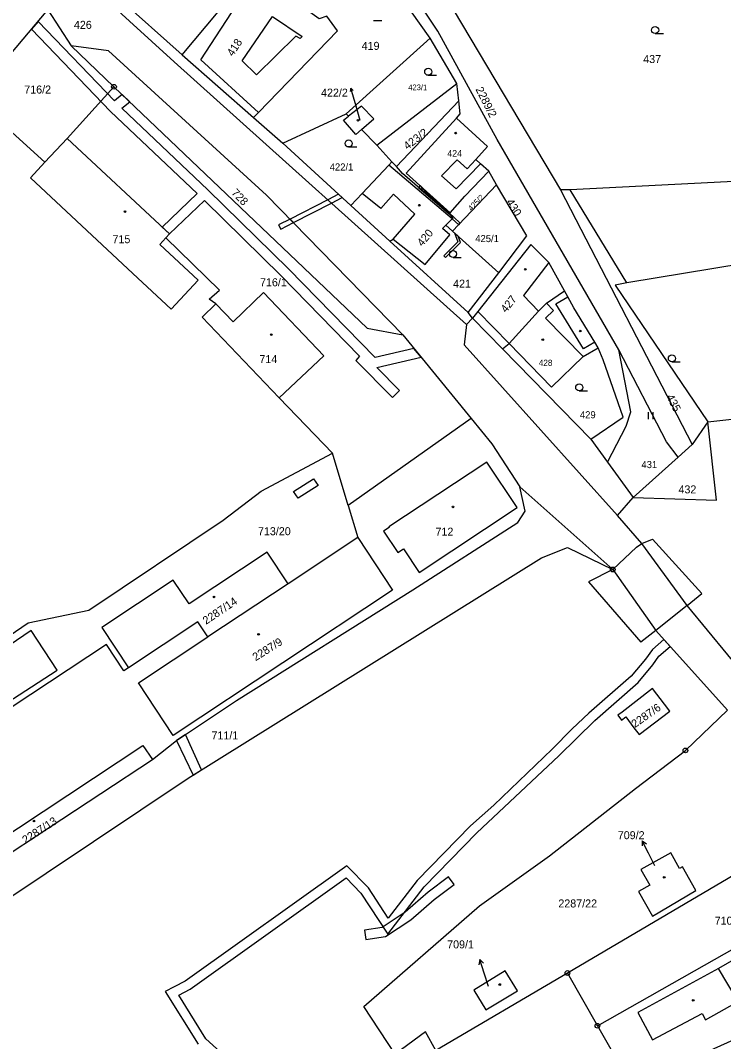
# Model space of a CAD drawing. Extents: x -504988 to -494607, y -1123820 to -1114018.
# Drawn here: x -496997.3 to -496848, y -1120700.3 to -1120483.5 of the extents above; entities that cross this region are included whole.
import ezdxf

# ---------------------------------------------------------------- set-up
doc = ezdxf.new("R2010")
doc.units = 0
for name, color, linetype in [('Hranice parcel', 7, 'Continuous'), ('Parcelní čísla', 7, 'Continuous'), ('Pop  PČ popisy', 7, 'Continuous'), ('Vnitřní kresba', 7, 'Continuous'), ('Věcná břemena k části', 7, 'Continuous'), ('Značky bodu BP', 7, 'Continuous'), ('Značky budov', 7, 'Continuous'), ('Značky kultur', 7, 'Continuous')]:
    doc.layers.add(name, color=color, linetype=linetype)

msp = doc.modelspace()

# ---------------------------------------------------------------- linework, layer by layer
at = {"layer": 'Hranice parcel'}
for p, q in [((-496910.28, -1120487.25), (-496931.3, -1120457.35)), ((-496980.45, -1120475.17), (-496962.91, -1120490.84)), ((-496962.91, -1120490.84), (-496949.37, -1120474.55)), ((-496991.45, -1120481.25), (-496986.51, -1120488.92)), ((-496928.11, -1120503.32), (-496910.28, -1120487.25)), ((-496904.62, -1120496.92), (-496910.28, -1120487.25)), ((-496986.51, -1120488.92), (-496977.41, -1120497.6)), ((-496962.91, -1120490.84), (-496947.76, -1120504.11)), ((-496921.6, -1120510.03), (-496904.62, -1120496.92)), ((-496904.23, -1120500.55), (-496904.62, -1120496.92)), ((-496977.41, -1120497.6), (-496987.36, -1120508.57)), ((-496992.06, -1120513.61), (-497007.31, -1120499.8)), ((-496917.46, -1120514.56), (-496904.23, -1120500.55)), ((-496941.57, -1120509.54), (-496928.11, -1120503.32)), ((-496927.59, -1120503.85), (-496928.11, -1120503.32)), ((-496947.76, -1120504.11), (-496941.57, -1120509.54)), ((-496921.6, -1120510.03), (-496924.83, -1120506.7)), ((-496987.36, -1120508.57), (-496992.06, -1120513.61)), ((-496941.57, -1120509.54), (-496927.11, -1120522.81)), ((-496918.41, -1120513.52), (-496921.6, -1120510.03)), ((-496917.46, -1120514.56), (-496918.41, -1120513.52)), ((-496916.13, -1120516), (-496917.46, -1120514.56)), ((-496906.26, -1120524.61), (-496916.13, -1120516)), ((-496896.17, -1120518.4), (-496897.86, -1120515.55)), ((-496811.5, -1120515.9), (-496880.58, -1120519.51)), ((-496896.17, -1120518.4), (-496905.52, -1120528.27)), ((-496882.64, -1120519.48), (-496854.69, -1120573.54)), ((-496880.58, -1120519.51), (-496882.64, -1120519.48)), ((-496868.53, -1120539.24), (-496880.58, -1120519.51)), ((-496927.11, -1120522.81), (-496918.88, -1120530.35)), ((-496905.45, -1120525.46), (-496906.26, -1120524.61)), ((-496905.52, -1120528.27), (-496906.95, -1120526.98)), ((-496895.69, -1120537.14), (-496905.52, -1120528.27)), ((-496918.88, -1120530.35), (-496902.22, -1120545.55)), ((-496902.22, -1120545.55), (-496895.69, -1120537.14)), ((-496901.27, -1120546.76), (-496902.22, -1120545.55)), ((-496901.27, -1120546.76), (-496894.93, -1120553.22)), ((-496916.08, -1120550.26), (-496901.56, -1120568.05)), ((-496894.93, -1120553.22), (-496893.52, -1120552.12)), ((-496894.93, -1120553.22), (-496876.16, -1120572.45)), ((-496930.99, -1120575.43), (-496942.31, -1120563.63)), ((-496901.56, -1120568.05), (-496927.7, -1120586.53)), ((-496851.36, -1120568.74), (-496854.69, -1120573.54)), ((-496851.36, -1120568.74), (-496840.65, -1120567.59)), ((-496876.16, -1120572.45), (-496872.63, -1120577.3)), ((-496946.16, -1120583.5), (-496930.99, -1120575.43)), ((-496927.7, -1120586.53), (-496930.99, -1120575.43)), ((-496854.69, -1120573.54), (-496857.65, -1120576.22)), ((-496872.63, -1120577.3), (-496867.16, -1120584.83)), ((-496867.16, -1120584.83), (-496857.65, -1120576.22)), ((-496891.25, -1120582.52), (-496871.51, -1120600.1)), ((-496927.7, -1120586.53), (-496925.65, -1120593.33)), ((-496925.65, -1120593.33), (-496940.42, -1120603.11)), ((-496940.42, -1120603.11), (-496957.48, -1120614.37)), ((-497003.77, -1120617.01), (-496995.6, -1120611.41)), ((-496856.1, -1120638.53), (-496847.18, -1120629.97)), ((-496971.29, -1120637.49), (-496969.26, -1120640.45)), ((-497022.21, -1120675.27), (-496969.26, -1120640.45)), ((-496823.76, -1120652.04), (-496881.14, -1120685.78)), ((-496874.78, -1120696.97), (-496812.85, -1120661.83)), ((-496881.14, -1120685.78), (-496874.78, -1120696.97)), ((-496917.69, -1120703), (-496924.38, -1120692.87))]:
    msp.add_line(p, q, dxfattribs=at)
for points in [[(-497083.51, -1120361.17), (-497068.27, -1120386.21), (-497064.86, -1120391.23), (-497055.98, -1120403.1), (-497051.98, -1120408.19), (-497036.29, -1120426.16), (-497025.6, -1120436.78), (-496964.64, -1120492.27), (-496902.58, -1120548.07), (-496901.27, -1120546.76)], [(-496870.25, -1120553.45), (-496896.08, -1120508.78), (-496908.69, -1120485.78), (-496920.45, -1120468), (-496933.79, -1120454.35), (-496940.92, -1120450.89), (-496953.48, -1120444.28)], [(-496912.61, -1120469.68), (-496905.22, -1120481.57), (-496882.64, -1120519.48)], [(-496947.76, -1120504.11), (-496946.75, -1120503.07), (-496929.97, -1120485.74), (-496932.25, -1120482.63), (-496933.87, -1120483.18), (-496936.3, -1120481.41), (-496935.13, -1120479.23), (-496940.4, -1120475.68), (-496942.89, -1120479.14), (-496948.48, -1120475.73), (-496949.37, -1120474.55)], [(-497007.31, -1120499.8), (-497003.46, -1120495.51), (-496991.45, -1120481.25)], [(-496916.08, -1120550.26), (-496945.04, -1120520.58), (-496978.58, -1120489.96), (-496986.51, -1120488.92)], [(-496977.41, -1120497.6), (-496923.68, -1120548.83), (-496916.08, -1120550.26)], [(-496924.83, -1120506.7), (-496922.22, -1120504.43), (-496924.86, -1120501.7), (-496927.59, -1120503.85)], [(-496897.86, -1120515.55), (-496899.61, -1120513.97), (-496900.6, -1120513.03), (-496898.11, -1120510.26), (-496904.72, -1120504.27), (-496903.9, -1120503.37), (-496904.23, -1120500.55)], [(-496924.83, -1120506.7), (-496926.05, -1120507.76), (-496928.67, -1120504.7), (-496927.59, -1120503.85)], [(-496966.39, -1120529.7), (-496965.61, -1120528.86), (-496987.36, -1120508.57)], [(-496774.36, -1120510.86), (-496807.07, -1120529.09), (-496868.53, -1120539.24)], [(-496966.39, -1120529.7), (-496967.69, -1120531.08), (-496959.55, -1120538.65), (-496965.29, -1120544.81), (-496973.42, -1120537.23), (-496995.17, -1120516.94), (-496992.06, -1120513.61)], [(-496918.41, -1120513.52), (-496919.09, -1120514.24), (-496924.72, -1120520.26), (-496927.11, -1120522.81)], [(-496906.26, -1120524.61), (-496906.01, -1120524.34), (-496902.94, -1120520.84), (-496897.86, -1120515.55)], [(-496895.69, -1120537.14), (-496889.74, -1120529.24), (-496896.17, -1120518.4)], [(-496906.95, -1120526.98), (-496905.61, -1120525.63), (-496905.45, -1120525.46)], [(-496918.88, -1120530.35), (-496918.11, -1120529.93), (-496911.32, -1120535.32), (-496906.1, -1120529.02), (-496907.66, -1120527.69), (-496906.95, -1120526.98)], [(-496955.82, -1120543.69), (-496957.18, -1120542.72), (-496955.04, -1120540.81), (-496966.39, -1120529.7)], [(-496881.78, -1120540.92), (-496885.11, -1120534.92), (-496888.9, -1120531.06), (-496900.16, -1120545.31), (-496901.27, -1120546.76)], [(-496868.53, -1120539.24), (-496870.99, -1120539.74), (-496851.36, -1120568.74)], [(-496942.31, -1120563.63), (-496932.89, -1120554.72), (-496945.66, -1120541.29), (-496952.12, -1120547.54), (-496955.82, -1120543.69)], [(-496893.52, -1120552.12), (-496887.25, -1120545.23), (-496885.56, -1120543.58), (-496881.78, -1120540.92)], [(-496874.59, -1120553.04), (-496875.32, -1120551.85), (-496879.76, -1120544.55), (-496881.07, -1120542.2), (-496881.78, -1120540.92)], [(-496942.31, -1120563.63), (-496958.68, -1120546.5), (-496955.82, -1120543.69)], [(-496893.52, -1120552.12), (-496884.49, -1120561.38), (-496877.83, -1120554.88), (-496874.59, -1120553.04)], [(-496876.16, -1120572.45), (-496869.32, -1120567.74), (-496873.57, -1120555.6), (-496874.59, -1120553.04)], [(-496872.63, -1120577.3), (-496868.66, -1120569.64), (-496867.67, -1120566.61), (-496870.25, -1120553.45)], [(-496857.65, -1120576.22), (-496860.12, -1120572.99), (-496870.25, -1120553.45)], [(-496901.56, -1120568.05), (-496897.2, -1120573.39), (-496891.25, -1120582.52)], [(-496867.16, -1120584.83), (-496849.5, -1120585.4), (-496851.36, -1120568.74)], [(-496917.14, -1120596.52), (-496915.93, -1120595.73), (-496912.63, -1120600.74), (-496891.83, -1120586.96), (-496898.24, -1120577.29), (-496919.04, -1120591.07), (-496918.98, -1120591.15), (-496920.19, -1120591.95), (-496917.14, -1120596.52)], [(-496995.6, -1120611.41), (-496982.78, -1120608.74), (-496954.25, -1120589.59), (-496946.16, -1120583.5)], [(-496969.26, -1120640.45), (-496964.12, -1120636.4), (-496951.37, -1120627.94), (-496913.96, -1120604.42), (-496891.7, -1120590.14), (-496890.08, -1120587.74), (-496891.25, -1120582.52)], [(-496871.51, -1120600.1), (-496866.45, -1120595.33), (-496865.34, -1120594.58), (-496870.5, -1120588.61), (-496867.16, -1120584.83)], [(-496925.65, -1120593.33), (-496918.27, -1120604.48), (-496964.84, -1120635.33), (-496972.24, -1120624.15), (-496957.48, -1120614.37)], [(-497022.03, -1120684.74), (-496961.65, -1120644.41), (-496886.64, -1120597.59), (-496881.11, -1120595.42), (-496871.51, -1120600.1)], [(-496940.42, -1120603.11), (-496944.87, -1120596.39), (-496961.48, -1120607.39), (-496964.82, -1120602.36), (-496980.01, -1120612.42), (-496974.34, -1120620.98)], [(-496833.73, -1120620.7), (-496842.8, -1120623.44), (-496855.74, -1120607.73), (-496862.4, -1120613.03), (-496847.18, -1120629.97)], [(-496957.48, -1120614.37), (-496959.58, -1120611.2), (-496974.34, -1120620.98)], [(-497014.72, -1120639.43), (-497007.53, -1120634.67), (-497008.27, -1120633.64), (-496989.5, -1120621.46), (-496994.97, -1120613.04), (-497002.87, -1120618.34), (-497003.77, -1120617.01)], [(-496974.34, -1120620.98), (-496975.31, -1120621.59), (-496978.97, -1120616.02), (-497003.25, -1120632), (-497014.72, -1120639.43)], [(-496860.5, -1120628.72), (-496863.06, -1120625.34), (-496869.51, -1120630.36), (-496870.44, -1120631.05), (-496869.63, -1120632.1), (-496868.75, -1120631.4), (-496867.02, -1120633.73), (-496865.94, -1120635.17), (-496859.42, -1120630.16), (-496860.5, -1120628.72)], [(-497022.21, -1120675.27), (-497024.15, -1120672.41), (-496971.29, -1120637.49)], [(-496924.38, -1120692.87), (-496899.79, -1120671.49), (-496884.96, -1120660.88), (-496866.67, -1120646.61), (-496856.1, -1120638.53)], [(-496856.73, -1120663.27), (-496857.34, -1120663.61), (-496859.22, -1120660.25), (-496865.54, -1120663.81), (-496863.66, -1120667.16), (-496866.02, -1120668.49), (-496863.07, -1120673.72), (-496853.91, -1120668.29), (-496856.73, -1120663.27)], [(-496807.49, -1120672.76), (-496810.8, -1120666.98), (-496815.43, -1120669.65), (-496817.18, -1120666.45), (-496849.08, -1120684.84), (-496866.16, -1120694.19), (-496863.11, -1120699.99), (-496852.53, -1120694.41), (-496851.81, -1120695.71), (-496844.89, -1120691.83), (-496843.73, -1120693.83), (-496807.49, -1120672.76)], [(-496881.14, -1120685.78), (-496909.1, -1120702.22), (-496911.28, -1120698.29), (-496917.69, -1120703)], [(-496894.33, -1120685.35), (-496901.02, -1120689.41), (-496898.46, -1120693.63), (-496891.77, -1120689.58), (-496894.33, -1120685.35)], [(-496874.78, -1120696.97), (-496869.05, -1120707.02), (-496853.61, -1120703.47), (-496837.12, -1120696.02)]]:
    msp.add_lwpolyline(points, dxfattribs=at)
at = {"layer": 'Pop  PČ popisy'}
for p, q in [((-496927.11, -1120497.87), (-496927.25, -1120498.6)), ((-496926.56, -1120499.8), (-496927.11, -1120497.87)), ((-496927.11, -1120497.87), (-496926.61, -1120498.42)), ((-496863.91, -1120660.35), (-496865.27, -1120657.68)), ((-496865.27, -1120657.68), (-496864.37, -1120658.34)), ((-496865.27, -1120657.68), (-496865.26, -1120658.8)), ((-496862.55, -1120663.03), (-496863.91, -1120660.35)), ((-496899.76, -1120682.93), (-496899.92, -1120684.03)), ((-496898.83, -1120685.78), (-496899.76, -1120682.93)), ((-496899.76, -1120682.93), (-496898.97, -1120683.72)), ((-496897.91, -1120688.64), (-496898.83, -1120685.78))]:
    msp.add_line(p, q, dxfattribs=at)
msp.add_lwpolyline([(-496925.11, -1120504.76), (-496926, -1120501.73), (-496926.56, -1120499.8)], dxfattribs=at)
at = {"layer": 'Vnitřní kresba'}
for p, q in [((-496958.97, -1120491.85), (-496948.48, -1120475.73)), ((-496950.21, -1120492.08), (-496943.74, -1120482.65)), ((-496943.74, -1120482.65), (-496937.46, -1120486.95)), ((-496938.77, -1120486.86), (-496947.13, -1120495.04)), ((-496937.85, -1120487.36), (-496938.77, -1120486.86)), ((-496937.46, -1120486.95), (-496937.85, -1120487.36)), ((-496946.75, -1120503.07), (-496958.97, -1120491.85)), ((-496947.13, -1120495.04), (-496950.21, -1120492.08)), ((-496915.36, -1120515.95), (-496904.72, -1120504.27)), ((-496905.61, -1120525.63), (-496919.09, -1120514.24)), ((-496904.54, -1120513.13), (-496907.89, -1120516.52)), ((-496904.74, -1120519.26), (-496899.61, -1120513.97)), ((-496902.42, -1120515.04), (-496904.54, -1120513.13)), ((-496900.6, -1120513.03), (-496902.42, -1120515.04)), ((-496906.01, -1120524.34), (-496915.36, -1120515.95)), ((-496907.89, -1120516.52), (-496904.74, -1120519.26)), ((-496920.79, -1120523.46), (-496924.72, -1120520.26)), ((-496918.1, -1120520.37), (-496920.79, -1120523.46)), ((-496913.54, -1120524.63), (-496918.1, -1120520.37)), ((-496918.11, -1120529.93), (-496913.54, -1120524.63)), ((-496885.11, -1120534.92), (-496890.47, -1120541.93)), ((-496890.47, -1120541.93), (-496887.25, -1120545.23)), ((-496883.61, -1120543.68), (-496881.07, -1120542.2)), ((-496884.1, -1120545.08), (-496885.79, -1120546.72)), ((-496885.56, -1120543.58), (-496884.1, -1120545.08)), ((-496877.73, -1120553.27), (-496883.61, -1120543.68)), ((-496893.52, -1120552.12), (-496900.16, -1120545.31)), ((-496885.79, -1120546.72), (-496877.83, -1120554.88)), ((-496902.58, -1120548.07), (-496903.04, -1120552.39)), ((-496903.04, -1120552.39), (-496870.5, -1120588.61)), ((-496875.32, -1120551.85), (-496877.73, -1120553.27)), ((-496939.28, -1120583.54), (-496935.02, -1120580.83)), ((-496935.02, -1120580.83), (-496934.09, -1120582.28)), ((-496938.31, -1120584.98), (-496939.28, -1120583.54)), ((-496934.09, -1120582.28), (-496938.31, -1120584.98)), ((-496865.34, -1120594.58), (-496863.1, -1120593.68)), ((-496855.74, -1120607.73), (-496865.34, -1120594.58)), ((-496863.1, -1120593.68), (-496852.61, -1120605.23)), ((-496871.51, -1120600.1), (-496876.64, -1120602.7)), ((-496871.51, -1120600.1), (-496862.4, -1120613.03)), ((-496876.64, -1120602.7), (-496865.55, -1120615.5)), ((-496855.74, -1120607.73), (-496852.61, -1120605.23)), ((-496862.4, -1120613.03), (-496865.55, -1120615.5)), ((-496844.89, -1120691.83), (-496849.08, -1120684.84))]:
    msp.add_line(p, q, dxfattribs=at)
at = {"layer": 'Věcná břemena k části'}
for points in [[(-496957.46, -1120519.45), (-496975.73, -1120502.13), (-496974.08, -1120500.78), (-496975.65, -1120499.27), (-496977.28, -1120500.6), (-496993.52, -1120483.71), (-496994.92, -1120485.37), (-496978.13, -1120502.84), (-496959.75, -1120520.26), (-496967.19, -1120527.39), (-496965.61, -1120528.86), (-496958.2, -1120521.76), (-496941.91, -1120537.75), (-496925.26, -1120554.78), (-496926.07, -1120555.69), (-496918.31, -1120563.6), (-496916.76, -1120562.1), (-496921.58, -1120557.18), (-496912.2, -1120555.01), (-496913.72, -1120553.15), (-496921.98, -1120555.05), (-496940.39, -1120536.23)], [(-496912.74, -1120518.96), (-496906.26, -1120524.61), (-496906.14, -1120524.48), (-496912.14, -1120519.03), (-496912.05, -1120518.92), (-496912.42, -1120518.59)], [(-496932.03, -1120521.59), (-496940.04, -1120525.7), (-496939.31, -1120526.45), (-496931.24, -1120522.3), (-496928.95, -1120521.13), (-496929.73, -1120520.41)], [(-496906.14, -1120524.48), (-496906.26, -1120524.61), (-496905.45, -1120525.46), (-496905.61, -1120525.63), (-496904.22, -1120526.9), (-496903.88, -1120526.54), (-496905.26, -1120525.27)], [(-496942.45, -1120526.94), (-496941.99, -1120527.83), (-496939.31, -1120526.45), (-496940.04, -1120525.7)], [(-496907.03, -1120533.87), (-496903.85, -1120530.66), (-496904.33, -1120529.34), (-496905.14, -1120528.62), (-496904.43, -1120530.54), (-496907.39, -1120533.51)], [(-496960.57, -1120643.74), (-496958.85, -1120642.66), (-496962.25, -1120635.16), (-496964.12, -1120636.4)], [(-496923.92, -1120678.66), (-496919.75, -1120678.06), (-496914.4, -1120674.47), (-496909.44, -1120670.2), (-496905.18, -1120666.97), (-496906.38, -1120665.37), (-496910.69, -1120668.64), (-496915.62, -1120672.87), (-496920.48, -1120676.15), (-496924.22, -1120676.69)]]:
    msp.add_lwpolyline(points, close=True, dxfattribs=at)
for points in [[(-496925.01, -1120668.85), (-496919.3, -1120677.53), (-496911.58, -1120667.47), (-496900.36, -1120656.01), (-496882.98, -1120639.66), (-496875.3, -1120632.14), (-496866.15, -1120624.07), (-496862.98, -1120620.35), (-496861.71, -1120618.51), (-496859.32, -1120616.45), (-496860.66, -1120614.96), (-496863.11, -1120617.07), (-496864.59, -1120619.17), (-496867.63, -1120622.72), (-496876.62, -1120630.64), (-496880.1, -1120633.92), (-496884.38, -1120638.22), (-496896.76, -1120650.11), (-496901.74, -1120654.56), (-496913.05, -1120666.11), (-496919.18, -1120674.15), (-496923.38, -1120667.68), (-496927.96, -1120663.03), (-496962.32, -1120687.54), (-496964.62, -1120688.74), (-496966.57, -1120689.68), (-496959.53, -1120700.89)], [(-496951.8, -1120705.31), (-496957.9, -1120699.73), (-496963.61, -1120690.47), (-496961.21, -1120689.2), (-496928.13, -1120665.6), (-496925.01, -1120668.85)]]:
    msp.add_lwpolyline(points, dxfattribs=at)
at = {"layer": 'Značky bodu BP'}
for centre, radius in [((-496977.41, -1120497.6), 0.5), ((-496977.41, -1120497.6), 0.0303), ((-496871.51, -1120600.1), 0.5), ((-496871.51, -1120600.1), 0.0303), ((-496856.1, -1120638.53), 0.5), ((-496856.1, -1120638.53), 0.0303), ((-496881.14, -1120685.78), 0.5), ((-496881.14, -1120685.78), 0.0303), ((-496874.78, -1120696.97), 0.5), ((-496874.78, -1120696.97), 0.0303)]:
    msp.add_circle(centre, radius, dxfattribs=at)
at = {"layer": 'Značky budov'}
for centre in [(-496925.61, -1120504.7), (-496904.86, -1120507.44), (-496912.6, -1120522.74), (-496975.09, -1120524.09), (-496890.08, -1120536.35), (-496878.41, -1120549.47), (-496944.02, -1120550.23), (-496886.38, -1120551.3), (-496905.44, -1120586.81), (-496956.17, -1120605.93), (-496946.72, -1120613.87), (-496994.41, -1120653.52), (-496860.59, -1120665.47), (-496895.5, -1120688.23), (-496854.43, -1120691.58)]:
    msp.add_circle(centre, 0.175, dxfattribs=at)
at = {"layer": 'Značky kultur'}
for p, q in [((-496922.29, -1120483.51), (-496920.54, -1120483.51)), ((-496862.52, -1120486.31), (-496860.77, -1120486.31)), ((-496910.7, -1120495.16), (-496908.95, -1120495.16)), ((-496927.59, -1120510.38), (-496925.84, -1120510.38)), ((-496905.42, -1120533.85), (-496903.67, -1120533.85)), ((-496858.96, -1120556.02), (-496857.21, -1120556.02)), ((-496878.64, -1120562.18), (-496876.89, -1120562.18)), ((-496863.92, -1120568.18), (-496863.92, -1120566.68)), ((-496862.92, -1120568.18), (-496862.92, -1120566.68))]:
    msp.add_line(p, q, dxfattribs=at)
for centre in [(-496862.52, -1120485.56), (-496910.7, -1120494.41), (-496927.59, -1120509.63), (-496905.42, -1120533.1), (-496858.96, -1120555.27), (-496878.64, -1120561.43)]:
    msp.add_circle(centre, 0.75, dxfattribs=at)

# ---------------------------------------------------------------- texts
at = {"layer": 'Parcelní čísla'}
for s, height, p in [('426', 1.7, (-496985.92, -1120485.3)), ('419', 1.7, (-496924.83, -1120489.76)), ('437', 1.7, (-496865.05, -1120492.56)), ('716/2', 1.7, (-496996.46, -1120499.04)), ('423/1', 1.2, (-496914.93, -1120498.32)), ('422/2', 1.7, (-496933.45, -1120499.7)), ('424', 1.4, (-496906.64, -1120512.44)), ('422/1', 1.5, (-496931.61, -1120515.38)), ('715', 1.7, (-496977.73, -1120530.81)), ('425/1', 1.5, (-496900.71, -1120530.58)), ('716/1', 1.7, (-496946.41, -1120539.96)), ('421', 1.7, (-496905.42, -1120540.26)), ('714', 1.7, (-496946.54, -1120556.28)), ('428', 1.3, (-496887.22, -1120556.86)), ('429', 1.5, (-496878.49, -1120567.99)), ('431', 1.5, (-496865.43, -1120578.57)), ('432', 1.7, (-496857.57, -1120583.94)), ('713/20', 1.7, (-496946.84, -1120592.82)), ('712', 1.7, (-496909.15, -1120592.92)), ('711/1', 1.7, (-496956.71, -1120636.17)), ('709/2', 1.7, (-496870.45, -1120657.37)), ('2287/22', 1.7, (-496883.07, -1120671.86)), ('710/1', 1.7, (-496849.87, -1120675.52)), ('709/1', 1.7, (-496906.68, -1120680.55))]:
    msp.add_text(s, height=height, dxfattribs=at).set_placement(p)
for s, height, rotation, p in [('418', 1.7, 57, (-496952.15, -1120491.27)), ('2289/2', 1.7, 297, (-496900.71, -1120498.13)), ('423/2', 1.7, 37, (-496915.14, -1120511.07)), ('728', 1.7, 314, (-496952.61, -1120520.24)), ('425/2', 1.2, 46, (-496901.52, -1120524.07)), ('430', 1.7, 302, (-496894.21, -1120522.06)), ('420', 1.7, 50, (-496911.95, -1120531.63)), ('427', 1.7, 51, (-496894.17, -1120545.71)), ('435', 1.7, 297, (-496860.19, -1120563.41)), ('2287/14', 1.7, 34, (-496957.86, -1120611.86)), ('2287/9', 1.7, 32, (-496947.35, -1120619.6)), ('2287/6', 1.7, 35, (-496866.82, -1120633.79)), ('2287/13', 1.7, 33, (-496996.21, -1120658.41))]:
    msp.add_text(s, height=height, rotation=rotation, dxfattribs=at).set_placement(p)

doc.saveas('drawing.dxf')
